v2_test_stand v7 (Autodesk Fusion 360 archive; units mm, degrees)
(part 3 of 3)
sketch "Sketch11" plane through (0, -1.7411, 0) normal (0, -1, 0) x axis (1, 0, 0)
  line L1 (18.05, 195.55) -> (20.15, 195.55)
  line L2 (18.05, 197.45) -> (18.05, 195.55)
  line L3 (16.6071, 197.8) -> (17.7, 197.8)
  line L4 (14.1525, 195.4904) -> (16.3596, 197.6975)
  line L5 (14.05, 189.7571) -> (14.05, 195.2429)
  line L6 (16.3596, 187.3025) -> (14.1525, 189.5096)
  line L7 (17.7, 187.2) -> (16.6071, 187.2)
  line L8 (18.05, 189.45) -> (18.05, 187.55)
  line L9 (20.15, 189.45) -> (18.05, 189.45)
  line L10 (20.15, 183.5) -> (20.15, 189.45)
  line L11 (13.05, 182.35) -> (19, 182.35)
  line L12 (13.05, 184.45) -> (13.05, 182.35)
  line L13 (14.95, 184.45) -> (13.05, 184.45)
  line L14 (15.3, 185.8929) -> (15.3, 184.8)
  line L15 (12.9904, 188.3475) -> (15.1975, 186.1404)
  line L16 (7.2571, 188.45) -> (12.7429, 188.45)
  line L17 (4.8025, 186.1404) -> (7.0096, 188.3475)
  line L18 (4.7, 184.8) -> (4.7, 185.8929)
  line L19 (6.95, 184.45) -> (5.05, 184.45)
  line L20 (6.95, 182.35) -> (6.95, 184.45)
  line L21 (1, 182.35) -> (6.95, 182.35)
  line L22 (-0.15, 189.45) -> (-0.15, 183.5)
  line L23 (1.95, 189.45) -> (-0.15, 189.45)
  line L24 (1.95, 187.55) -> (1.95, 189.45)
  line L25 (3.3929, 187.2) -> (2.3, 187.2)
  line L26 (5.8475, 189.5096) -> (3.6404, 187.3025)
  line L27 (5.95, 195.2429) -> (5.95, 189.7571)
  line L28 (3.6404, 197.6975) -> (5.8475, 195.4904)
  line L29 (2.3, 197.8) -> (3.3929, 197.8)
  line L30 (1.95, 195.55) -> (1.95, 197.45)
  line L31 (-0.15, 195.55) -> (1.95, 195.55)
  line L32 (-0.15, 201.5) -> (-0.15, 195.55)
  line L33 (6.95, 202.65) -> (1, 202.65)
  line L34 (6.95, 200.55) -> (6.95, 202.65)
  line L35 (5.05, 200.55) -> (6.95, 200.55)
  line L36 (4.7, 199.1071) -> (4.7, 200.2)
  line L37 (7.0096, 196.6525) -> (4.8025, 198.8596)
  line L38 (12.7429, 196.55) -> (7.2571, 196.55)
  line L39 (15.1975, 198.8596) -> (12.9904, 196.6525)
  line L40 (15.3, 200.2) -> (15.3, 199.1071)
  line L41 (13.05, 200.55) -> (14.95, 200.55)
  line L42 (13.05, 202.65) -> (13.05, 200.55)
  line L43 (19, 202.65) -> (13.05, 202.65)
  line L44 (20.15, 195.55) -> (20.15, 201.5)
  line L45 (-30.5619, 135.124) -> (-30.5619, 209.2124)
  line L46 (-23.8456, 80.7701) -> (-36.2272, 103.4157)
  line L47 (54.2589, 103.4157) -> (41.8773, 80.7701)
  line L48 (48.5935, 209.2124) -> (48.5935, 135.124)
  line L49 (-15.5619, 224.2124) -> (33.5935, 224.2124)
  arc A1 centre (17.7, 197.45) radius 0.35 clockwise from (17.7, 197.8) to (18.05, 197.45)
  arc A2 centre (16.6071, 197.45) radius 0.35 clockwise from (16.3596, 197.6975) to (16.6071, 197.8)
  arc A3 centre (14.4, 195.2429) radius 0.35 clockwise from (14.05, 195.2429) to (14.1525, 195.4904)
  arc A4 centre (14.4, 189.7571) radius 0.35 clockwise from (14.1525, 189.5096) to (14.05, 189.7571)
  arc A5 centre (16.6071, 187.55) radius 0.35 clockwise from (16.6071, 187.2) to (16.3596, 187.3025)
  arc A6 centre (17.7, 187.55) radius 0.35 clockwise from (18.05, 187.55) to (17.7, 187.2)
  arc A7 centre (19, 183.5) radius 1.15 clockwise from (20.15, 183.5) to (19, 182.35)
  arc A8 centre (14.95, 184.8) radius 0.35 clockwise from (15.3, 184.8) to (14.95, 184.45)
  arc A9 centre (14.95, 185.8929) radius 0.35 clockwise from (15.1975, 186.1404) to (15.3, 185.8929)
  arc A10 centre (12.7429, 188.1) radius 0.35 clockwise from (12.7429, 188.45) to (12.9904, 188.3475)
  arc A11 centre (7.2571, 188.1) radius 0.35 clockwise from (7.0096, 188.3475) to (7.2571, 188.45)
  arc A12 centre (5.05, 185.8929) radius 0.35 clockwise from (4.7, 185.8929) to (4.8025, 186.1404)
  arc A13 centre (5.05, 184.8) radius 0.35 clockwise from (5.05, 184.45) to (4.7, 184.8)
  arc A14 centre (1, 183.5) radius 1.15 clockwise from (1, 182.35) to (-0.15, 183.5)
  arc A15 centre (2.3, 187.55) radius 0.35 clockwise from (2.3, 187.2) to (1.95, 187.55)
  arc A16 centre (3.3929, 187.55) radius 0.35 clockwise from (3.6404, 187.3025) to (3.3929, 187.2)
  arc A17 centre (5.6, 189.7571) radius 0.35 clockwise from (5.95, 189.7571) to (5.8475, 189.5096)
  arc A18 centre (5.6, 195.2429) radius 0.35 clockwise from (5.8475, 195.4904) to (5.95, 195.2429)
  arc A19 centre (3.3929, 197.45) radius 0.35 clockwise from (3.3929, 197.8) to (3.6404, 197.6975)
  arc A20 centre (2.3, 197.45) radius 0.35 clockwise from (1.95, 197.45) to (2.3, 197.8)
  arc A21 centre (1, 201.5) radius 1.15 clockwise from (-0.15, 201.5) to (1, 202.65)
  arc A22 centre (5.05, 200.2) radius 0.35 clockwise from (4.7, 200.2) to (5.05, 200.55)
  arc A23 centre (5.05, 199.1071) radius 0.35 clockwise from (4.8025, 198.8596) to (4.7, 199.1071)
  arc A24 centre (7.2571, 196.9) radius 0.35 clockwise from (7.2571, 196.55) to (7.0096, 196.6525)
  arc A25 centre (12.7429, 196.9) radius 0.35 clockwise from (12.9904, 196.6525) to (12.7429, 196.55)
  arc A26 centre (14.95, 199.1071) radius 0.35 clockwise from (15.3, 199.1071) to (15.1975, 198.8596)
  arc A27 centre (14.95, 200.2) radius 0.35 clockwise from (14.95, 200.55) to (15.3, 200.2)
  arc A28 centre (19, 201.5) radius 1.15 clockwise from (19, 202.65) to (20.15, 201.5)
  arc A29 centre (-122.1289, 135.124) radius 91.567 clockwise from (-30.5619, 135.124) to (-36.2272, 103.4157)
  arc A30 centre (9.0158, 20.6671) radius 68.5 clockwise from (-23.8456, 80.7701) to (41.8773, 80.7701)
  arc A31 centre (140.1605, 135.124) radius 91.567 clockwise from (54.2589, 103.4157) to (48.5935, 135.124)
  arc A32 centre (33.5935, 209.2124) radius 15 clockwise from (33.5935, 224.2124) to (48.5935, 209.2124)
  arc A33 centre (-15.5619, 209.2124) radius 15 clockwise from (-30.5619, 209.2124) to (-15.5619, 224.2124)
  circle C1 centre (9.0158, 20.6671) radius 103.756
  concentric A30 C1
sketch "Sketch12" plane through (0, 39.5049, 0) normal (0, 1, 0) x axis (-1, 0, 0)
  line L1 (-20.15, 195.55) -> (-18.05, 195.55)
  line L2 (-20.15, 201.5) -> (-20.15, 195.55)
  line L3 (-13.05, 202.65) -> (-19, 202.65)
  line L4 (-13.05, 200.55) -> (-13.05, 202.65)
  line L5 (-14.95, 200.55) -> (-13.05, 200.55)
  line L6 (-15.3, 199.1071) -> (-15.3, 200.2)
  line L7 (-12.9904, 196.6525) -> (-15.1975, 198.8596)
  line L8 (-7.2571, 196.55) -> (-12.7429, 196.55)
  line L9 (-4.8025, 198.8596) -> (-7.0096, 196.6525)
  line L10 (-4.7, 200.2) -> (-4.7, 199.1071)
  line L11 (-6.95, 200.55) -> (-5.05, 200.55)
  line L12 (-6.95, 202.65) -> (-6.95, 200.55)
  line L13 (-1, 202.65) -> (-6.95, 202.65)
  line L14 (0.15, 195.55) -> (0.15, 201.5)
  line L15 (-1.95, 195.55) -> (0.15, 195.55)
  line L16 (-1.95, 197.45) -> (-1.95, 195.55)
  line L17 (-3.3929, 197.8) -> (-2.3, 197.8)
  line L18 (-5.8475, 195.4904) -> (-3.6404, 197.6975)
  line L19 (-5.95, 189.7571) -> (-5.95, 195.2429)
  line L20 (-3.6404, 187.3025) -> (-5.8475, 189.5096)
  line L21 (-2.3, 187.2) -> (-3.3929, 187.2)
  line L22 (-1.95, 189.45) -> (-1.95, 187.55)
  line L23 (0.15, 189.45) -> (-1.95, 189.45)
  line L24 (0.15, 183.5) -> (0.15, 189.45)
  line L25 (-6.95, 182.35) -> (-1, 182.35)
  line L26 (-6.95, 184.45) -> (-6.95, 182.35)
  line L27 (-5.05, 184.45) -> (-6.95, 184.45)
  line L28 (-4.7, 185.8929) -> (-4.7, 184.8)
  line L29 (-7.0096, 188.3475) -> (-4.8025, 186.1404)
  line L30 (-12.7429, 188.45) -> (-7.2571, 188.45)
  line L31 (-15.1975, 186.1404) -> (-12.9904, 188.3475)
  line L32 (-15.3, 184.8) -> (-15.3, 185.8929)
  line L33 (-13.05, 184.45) -> (-14.95, 184.45)
  line L34 (-13.05, 182.35) -> (-13.05, 184.45)
  line L35 (-19, 182.35) -> (-13.05, 182.35)
  line L36 (-20.15, 189.45) -> (-20.15, 183.5)
  line L37 (-18.05, 189.45) -> (-20.15, 189.45)
  line L38 (-18.05, 187.55) -> (-18.05, 189.45)
  line L39 (-16.6071, 187.2) -> (-17.7, 187.2)
  line L40 (-14.1525, 189.5096) -> (-16.3596, 187.3025)
  line L41 (-14.05, 195.2429) -> (-14.05, 189.7571)
  line L42 (-16.3596, 197.6975) -> (-14.1525, 195.4904)
  line L43 (-17.7, 197.8) -> (-16.6071, 197.8)
  line L44 (-18.05, 195.55) -> (-18.05, 197.45)
  line L45 (30.5619, 209.2124) -> (30.5619, 135.124)
  line L46 (-33.5935, 224.2124) -> (15.5619, 224.2124)
  line L47 (-48.5935, 135.124) -> (-48.5935, 209.2124)
  arc A1 centre (-140.1605, 135.124) radius 91.567 clockwise from (-48.5935, 135.124) to (-71.1726, 74.9146)
  arc A2 centre (-9.0158, 20.6671) radius 82.5 clockwise from (53.1409, 74.9146) to (-71.1726, 74.9146)
  arc A3 centre (122.1289, 135.124) radius 91.567 clockwise from (53.1409, 74.9146) to (30.5619, 135.124)
  circle C1 centre (-9.0158, 20.6671) radius 78.8
  arc A4 centre (-19, 201.5) radius 1.15 clockwise from (-20.15, 201.5) to (-19, 202.65)
  arc A5 centre (-14.95, 200.2) radius 0.35 clockwise from (-15.3, 200.2) to (-14.95, 200.55)
  arc A6 centre (-14.95, 199.1071) radius 0.35 clockwise from (-15.1975, 198.8596) to (-15.3, 199.1071)
  arc A7 centre (-12.7429, 196.9) radius 0.35 clockwise from (-12.7429, 196.55) to (-12.9904, 196.6525)
  arc A8 centre (-7.2571, 196.9) radius 0.35 clockwise from (-7.0096, 196.6525) to (-7.2571, 196.55)
  arc A9 centre (-5.05, 199.1071) radius 0.35 clockwise from (-4.7, 199.1071) to (-4.8025, 198.8596)
  arc A10 centre (-5.05, 200.2) radius 0.35 clockwise from (-5.05, 200.55) to (-4.7, 200.2)
  arc A11 centre (-1, 201.5) radius 1.15 clockwise from (-1, 202.65) to (0.15, 201.5)
  arc A12 centre (-2.3, 197.45) radius 0.35 clockwise from (-2.3, 197.8) to (-1.95, 197.45)
  arc A13 centre (-3.3929, 197.45) radius 0.35 clockwise from (-3.6404, 197.6975) to (-3.3929, 197.8)
  arc A14 centre (-5.6, 195.2429) radius 0.35 clockwise from (-5.95, 195.2429) to (-5.8475, 195.4904)
  arc A15 centre (-5.6, 189.7571) radius 0.35 clockwise from (-5.8475, 189.5096) to (-5.95, 189.7571)
  arc A16 centre (-3.3929, 187.55) radius 0.35 clockwise from (-3.3929, 187.2) to (-3.6404, 187.3025)
  arc A17 centre (-2.3, 187.55) radius 0.35 clockwise from (-1.95, 187.55) to (-2.3, 187.2)
  arc A18 centre (-1, 183.5) radius 1.15 clockwise from (0.15, 183.5) to (-1, 182.35)
  arc A19 centre (-5.05, 184.8) radius 0.35 clockwise from (-4.7, 184.8) to (-5.05, 184.45)
  arc A20 centre (-5.05, 185.8929) radius 0.35 clockwise from (-4.8025, 186.1404) to (-4.7, 185.8929)
  arc A21 centre (-7.2571, 188.1) radius 0.35 clockwise from (-7.2571, 188.45) to (-7.0096, 188.3475)
  arc A22 centre (-12.7429, 188.1) radius 0.35 clockwise from (-12.9904, 188.3475) to (-12.7429, 188.45)
  arc A23 centre (-14.95, 185.8929) radius 0.35 clockwise from (-15.3, 185.8929) to (-15.1975, 186.1404)
  arc A24 centre (-14.95, 184.8) radius 0.35 clockwise from (-14.95, 184.45) to (-15.3, 184.8)
  arc A25 centre (-19, 183.5) radius 1.15 clockwise from (-19, 182.35) to (-20.15, 183.5)
  arc A26 centre (-17.7, 187.55) radius 0.35 clockwise from (-17.7, 187.2) to (-18.05, 187.55)
  arc A27 centre (-16.6071, 187.55) radius 0.35 clockwise from (-16.3596, 187.3025) to (-16.6071, 187.2)
  arc A28 centre (-14.4, 189.7571) radius 0.35 clockwise from (-14.05, 189.7571) to (-14.1525, 189.5096)
  arc A29 centre (-14.4, 195.2429) radius 0.35 clockwise from (-14.1525, 195.4904) to (-14.05, 195.2429)
  arc A30 centre (-16.6071, 197.45) radius 0.35 clockwise from (-16.6071, 197.8) to (-16.3596, 197.6975)
  arc A31 centre (-17.7, 197.45) radius 0.35 clockwise from (-18.05, 197.45) to (-17.7, 197.8)
  arc A32 centre (15.5619, 209.2124) radius 15 clockwise from (15.5619, 224.2124) to (30.5619, 209.2124)
  arc A33 centre (-33.5935, 209.2124) radius 15 clockwise from (-48.5935, 209.2124) to (-33.5935, 224.2124)
sketch "Sketch13" plane through (0, -1.7411, 0) normal (0, -1, 0) x axis (1, 0, 0)
  line L1 (48.6641, 138.718) -> (-30.6324, 138.718)
  arc A1 centre (-122.1289, 135.124) radius 91.567 clockwise from (-30.5619, 135.124) to (-53.1409, 74.9146)
  arc A2 centre (-122.1289, 135.124) radius 91.567 clockwise from (-30.5619, 135.124) to (-36.2272, 103.4157)
  arc A3 centre (140.1605, 135.124) radius 91.567 clockwise from (71.1726, 74.9146) to (48.5935, 135.124)
  point P11 (-30.6324, 138.718)
  point P12 (48.6641, 138.718)
  coincident A1 P11
  coincident A2 P11
  coincident A3 P12
  horizontal L1
sketch "Sketch3" plane through (0, 322.2748, 236.7742) normal (0, 0.8059, 0.5921) x axis (1, 0, 0)
  line L1 (8.7817, -59.4833) -> (8.7817, -57.9833)
  line L2 (2.1888, -60.1833) -> (8.0817, -60.1833)
  line L3 (-16.6632, -41.6212) -> (1.6939, -59.9783)
  line L4 (-16.8683, -38.5404) -> (-16.8683, -41.1262)
  line L5 (1.8989, -19.4833) -> (-16.6632, -38.0454)
  line L6 (8.7817, -19.4833) -> (1.8989, -19.4833)
  line L7 (8.7817, -22.7427) -> (8.7817, -19.4833)
  line L8 (12.3817, -19.4833) -> (12.3817, -22.7427)
  line L9 (19.2646, -19.4833) -> (12.3817, -19.4833)
  line L10 (37.8267, -38.0454) -> (19.2646, -19.4833)
  line L11 (38.0317, -41.1262) -> (38.0317, -38.5404)
  line L12 (19.4696, -59.9783) -> (37.8267, -41.6212)
  line L13 (13.0817, -60.1833) -> (18.9746, -60.1833)
  line L14 (12.3817, -57.9833) -> (12.3817, -59.4833)
  line L15 (9.0817, -57.6833) -> (12.0817, -57.6833)
  line L16 (-1.2287, -62.9008) -> (-19.5858, -44.5437)
  line L17 (8.0817, -64.3164) -> (2.1888, -64.3164)
  line L18 (18.9746, -64.3164) -> (13.0817, -64.3164)
  line L19 (40.7492, -44.5437) -> (22.3921, -62.9008)
  line L20 (42.1648, -38.5404) -> (42.1648, -41.1262)
  line L21 (27.2258, -21.5995) -> (40.7492, -35.1229)
  curve K1 (27.2258, -21.5995) -> (22.991, -15.3502)
  line L22 (-2.018, -15.3502) -> (22.991, -15.3502)
  curve K2 (-2.018, -15.3502) -> (-6.3915, -21.9286)
  line L23 (-19.5858, -35.1229) -> (-6.3915, -21.9286)
  line L24 (-21.0013, -41.1262) -> (-21.0013, -38.5404)
  line L25 (12.3817, -19.4833) -> (8.7817, -19.4833)
  line L26 (13.0817, -60.1833) -> (8.0817, -60.1833)
  arc A1 centre (8.0817, -59.4833) radius 0.7 clockwise from (8.7817, -59.4833) to (8.0817, -60.1833)
  arc A2 centre (2.1888, -59.4833) radius 0.7 clockwise from (2.1888, -60.1833) to (1.6939, -59.9783)
  arc A3 centre (-16.1683, -41.1262) radius 0.7 clockwise from (-16.6632, -41.6212) to (-16.8683, -41.1262)
  arc A4 centre (-16.1683, -38.5404) radius 0.7 clockwise from (-16.8683, -38.5404) to (-16.6632, -38.0454)
  arc A5 centre (10.5817, -39.8333) radius 17.1851 clockwise from (8.7817, -22.7427) to (12.3817, -22.7427)
  arc A6 centre (37.3317, -38.5404) radius 0.7 clockwise from (37.8267, -38.0454) to (38.0317, -38.5404)
  arc A7 centre (37.3317, -41.1262) radius 0.7 clockwise from (38.0317, -41.1262) to (37.8267, -41.6212)
  arc A8 centre (18.9746, -59.4833) radius 0.7 clockwise from (19.4696, -59.9783) to (18.9746, -60.1833)
  arc A9 centre (13.0817, -59.4833) radius 0.7 clockwise from (13.0817, -60.1833) to (12.3817, -59.4833)
  arc A10 centre (12.0817, -57.9833) radius 0.3 clockwise from (12.0817, -57.6833) to (12.3817, -57.9833)
  arc A11 centre (9.0817, -57.9833) radius 0.3 clockwise from (8.7817, -57.9833) to (9.0817, -57.6833)
  arc A12 centre (-16.1683, -41.1262) radius 4.8331 clockwise from (-19.5858, -44.5437) to (-21.0013, -41.1262)
  arc A13 centre (2.1888, -59.4833) radius 4.8331 clockwise from (2.1888, -64.3164) to (-1.2287, -62.9008)
  arc A14 centre (8.0817, -59.4833) radius 4.8331 clockwise from (10.5817, -63.6195) to (8.0817, -64.3164)
  arc A15 centre (13.0817, -59.4833) radius 4.8331 clockwise from (13.0817, -64.3164) to (10.5817, -63.6195)
  arc A16 centre (18.9746, -59.4833) radius 4.8331 clockwise from (22.3921, -62.9008) to (18.9746, -64.3164)
  arc A17 centre (37.3317, -41.1262) radius 4.8331 clockwise from (42.1648, -41.1262) to (40.7492, -44.5437)
  arc A18 centre (37.3317, -38.5404) radius 4.8331 clockwise from (40.7492, -35.1229) to (42.1648, -38.5404)
  arc A19 centre (-16.1683, -38.5404) radius 4.8331 clockwise from (-21.0013, -38.5404) to (-19.5858, -35.1229)
  point P16 (8.7817, -19.4833)
  point P58 (8.7817, -19.4833)
  point P20 (12.3817, -19.4833)
  point P59 (12.3817, -19.4833)
  point P4 (8.0817, -60.1833)
  point P60 (8.0817, -60.1833)
  point P31 (13.0817, -60.1833)
  point P61 (13.0817, -60.1833)
  coincident P16 P58
  coincident P20 P59
  coincident P4 P60
  coincident P31 P61
extrude "Extrude4" cut sketch "Sketch3" profile of L1 A1 L7 A5 L8 A9 L14 A10 L15 A11 L25 L26 against normal blind 2.645
sketch "Sketch4" plane through (0, 322.2748, 236.7742) normal (0, 0.8059, 0.5921) x axis (1, 0, 0)
  line L1 (2.1888, -60.1833) -> (18.9746, -60.1833)
  line L2 (-16.6632, -41.6212) -> (1.6939, -59.9783)
  line L3 (-16.8683, -38.5404) -> (-16.8683, -41.1262)
  line L4 (1.8989, -19.4833) -> (-16.6632, -38.0454)
  line L5 (19.2646, -19.4833) -> (1.8989, -19.4833)
  line L6 (37.8267, -38.0454) -> (19.2646, -19.4833)
  line L7 (38.0317, -41.1262) -> (38.0317, -38.5404)
  line L8 (19.4696, -59.9783) -> (37.8267, -41.6212)
  line L9 (-1.2287, -62.9008) -> (-19.5858, -44.5437)
  line L10 (8.0817, -64.3164) -> (2.1888, -64.3164)
  line L11 (18.9746, -64.3164) -> (13.0817, -64.3164)
  line L12 (40.7492, -44.5437) -> (22.3921, -62.9008)
  line L13 (42.1648, -38.5404) -> (42.1648, -41.1262)
  line L14 (27.2258, -21.5995) -> (40.7492, -35.1229)
  curve K1 (27.2258, -21.5995) -> (22.991, -15.3502)
  line L15 (-2.018, -15.3502) -> (22.991, -15.3502)
  curve K2 (-2.018, -15.3502) -> (-6.3915, -21.9286)
  line L16 (-19.5858, -35.1229) -> (-6.3915, -21.9286)
  line L17 (-21.0013, -41.1262) -> (-21.0013, -38.5404)
  line L18 (38.1095, -37.7626) -> (19.4303, -19.0833)
  line L19 (19.4303, -19.0833) -> (1.7332, -19.0833)
  line L20 (1.7332, -19.0833) -> (-16.9461, -37.7626)
  line L21 (-17.2683, -38.5404) -> (-17.2683, -41.1262)
  line L22 (-16.9461, -41.904) -> (1.411, -60.2611)
  line L23 (2.1888, -60.5833) -> (18.9746, -60.5833)
  line L24 (19.7524, -60.2611) -> (38.1095, -41.904)
  line L25 (38.4317, -41.1262) -> (38.4317, -38.5404)
  arc A1 centre (2.1888, -59.4833) radius 0.7 clockwise from (2.1888, -60.1833) to (1.6939, -59.9783)
  arc A2 centre (-16.1683, -41.1262) radius 0.7 clockwise from (-16.6632, -41.6212) to (-16.8683, -41.1262)
  arc A3 centre (-16.1683, -38.5404) radius 0.7 clockwise from (-16.8683, -38.5404) to (-16.6632, -38.0454)
  arc A4 centre (37.3317, -38.5404) radius 0.7 clockwise from (37.8267, -38.0454) to (38.0317, -38.5404)
  arc A5 centre (37.3317, -41.1262) radius 0.7 clockwise from (38.0317, -41.1262) to (37.8267, -41.6212)
  arc A6 centre (18.9746, -59.4833) radius 0.7 clockwise from (19.4696, -59.9783) to (18.9746, -60.1833)
  arc A7 centre (-16.1683, -41.1262) radius 4.8331 clockwise from (-19.5858, -44.5437) to (-21.0013, -41.1262)
  arc A8 centre (2.1888, -59.4833) radius 4.8331 clockwise from (2.1888, -64.3164) to (-1.2287, -62.9008)
  arc A9 centre (8.0817, -59.4833) radius 4.8331 clockwise from (10.5817, -63.6195) to (8.0817, -64.3164)
  arc A10 centre (13.0817, -59.4833) radius 4.8331 clockwise from (13.0817, -64.3164) to (10.5817, -63.6195)
  arc A11 centre (18.9746, -59.4833) radius 4.8331 clockwise from (22.3921, -62.9008) to (18.9746, -64.3164)
  arc A12 centre (37.3317, -41.1262) radius 4.8331 clockwise from (42.1648, -41.1262) to (40.7492, -44.5437)
  arc A13 centre (37.3317, -38.5404) radius 4.8331 clockwise from (40.7492, -35.1229) to (42.1648, -38.5404)
  arc A14 centre (-16.1683, -38.5404) radius 4.8331 clockwise from (-21.0013, -38.5404) to (-19.5858, -35.1229)
  arc A15 centre (37.3317, -38.5404) radius 1.1 clockwise from (38.1095, -37.7626) to (38.4317, -38.5404)
  arc A16 centre (-16.1683, -38.5404) radius 1.1 clockwise from (-17.2683, -38.5404) to (-16.9461, -37.7626)
  arc A17 centre (-16.1683, -41.1262) radius 1.1 clockwise from (-16.9461, -41.904) to (-17.2683, -41.1262)
  arc A18 centre (2.1888, -59.4833) radius 1.1 clockwise from (2.1888, -60.5833) to (1.411, -60.2611)
  arc A19 centre (18.9746, -59.4833) radius 1.1 clockwise from (19.7524, -60.2611) to (18.9746, -60.5833)
  arc A20 centre (37.3317, -41.1262) radius 1.1 clockwise from (38.4317, -41.1262) to (38.1095, -41.904)
  dimension "d171" = -0.4
extrude "Extrude5" cut sketch "Sketch4" profile of L1 A1 L2 A2 L3 A3 L4 L5 L6 A4 L7 A5 L8 A6 L23 L18 L22 A20 A17 A19 A16 L20 L19 L25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 against normal blind 2.645
position "Position3"
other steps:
create_component "CreateComponent2"
create_component "CreateComponent3"
create_component "CreateComponent4"
create_component "CreateComponent5"
create_component "CreateComponent6"
create_component "CreateComponent7"

design "DFR0523"
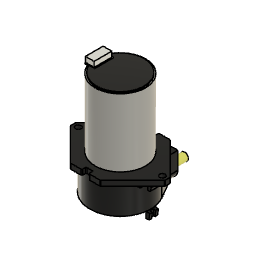
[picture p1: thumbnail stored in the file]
description: STEP AP214
part number: DFR0523
base_feature "Base Feature"

design "157mm_top_lid"
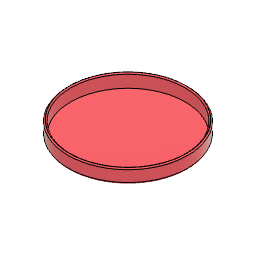
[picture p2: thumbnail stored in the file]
sketch "Sketch1" plane through (0, 0, 0) normal (0, 1, 0) x axis (1, 0, 0)
  circle C1 centre (0, 0) radius 78.5
  point P1 (0, 0)
  point P2 (0, 0)
  coincident P1 P2
  dimension "d1" diameter C1 = 157
extrude "Extrude1" new body sketch "Sketch1" along normal blind 1.6
sketch "Sketch2" plane through (0, 1.6, 0) normal (0, 1, 0) x axis (-1, 0, 0)
  circle C1 centre (0, 0) radius 78.5
  circle C2 centre (0, 0) radius 75.2
  dimension "d4" = -3.3
extrude "Extrude2" add sketch "Sketch2" along normal blind 17.5
fillet "Fillet1" radius 1.52 3

design "2020_extrusion_385"
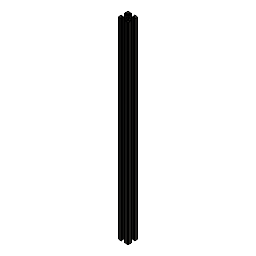
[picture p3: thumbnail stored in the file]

design "150mm_glass_base"
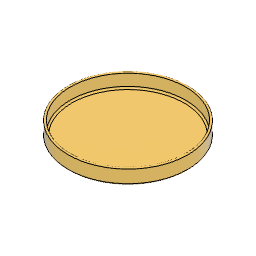
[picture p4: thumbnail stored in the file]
sketch "Sketch1" plane through (0, 0, 0) normal (0, 1, 0) x axis (1, 0, 0)
  circle C1 centre (0, 0) radius 71.15
  circle C2 centre (0, 0) radius 74.5
  point P1 (0, 0)
  point P2 (0, 0)
  coincident P1 P2
  dimension "d2" = 3.35
  dimension "d14" diameter C2 = 149
extrude "Extrude1" new body sketch "Sketch1" along normal blind 1.56 bodies "Base"
sketch "Sketch2" plane through (0, 1.56, 0) normal (0, 1, 0) x axis (-1, 0, 0)
  circle C1 centre (0, 0) radius 74.5
  circle C2 centre (0, 0) radius 72
  dimension "d5" = -2.5
extrude "Extrude2" add sketch "Sketch2" along normal blind 17.5
fillet "Fillet1" radius 2 1.25
fillet "Fillet2" radius 2
named bodies: "Base"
